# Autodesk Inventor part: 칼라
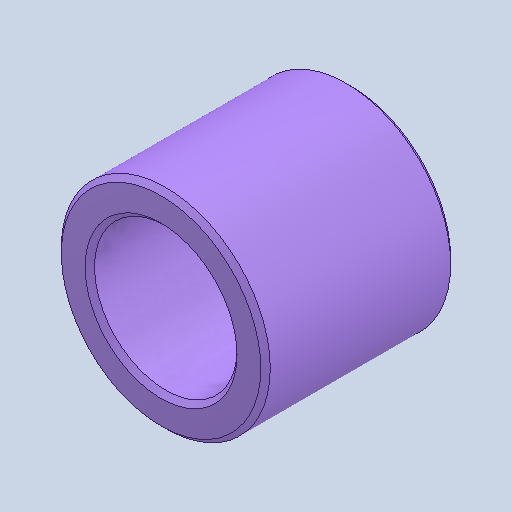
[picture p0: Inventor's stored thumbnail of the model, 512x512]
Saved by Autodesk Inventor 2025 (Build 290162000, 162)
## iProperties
Created: 2024-07
Part Number: 칼라
Material: 스테인리스강
Document SubType Name: Modeling
Designer: Administrator
Density: 8.08 g/cm^3
Appearance: 기본값
Author: jhkim
Sending System: Autodesk Inventor 2025
Preprocessor: ST-DEVELOPER v20
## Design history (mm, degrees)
feature "솔리드1"
node "솔리드2"
